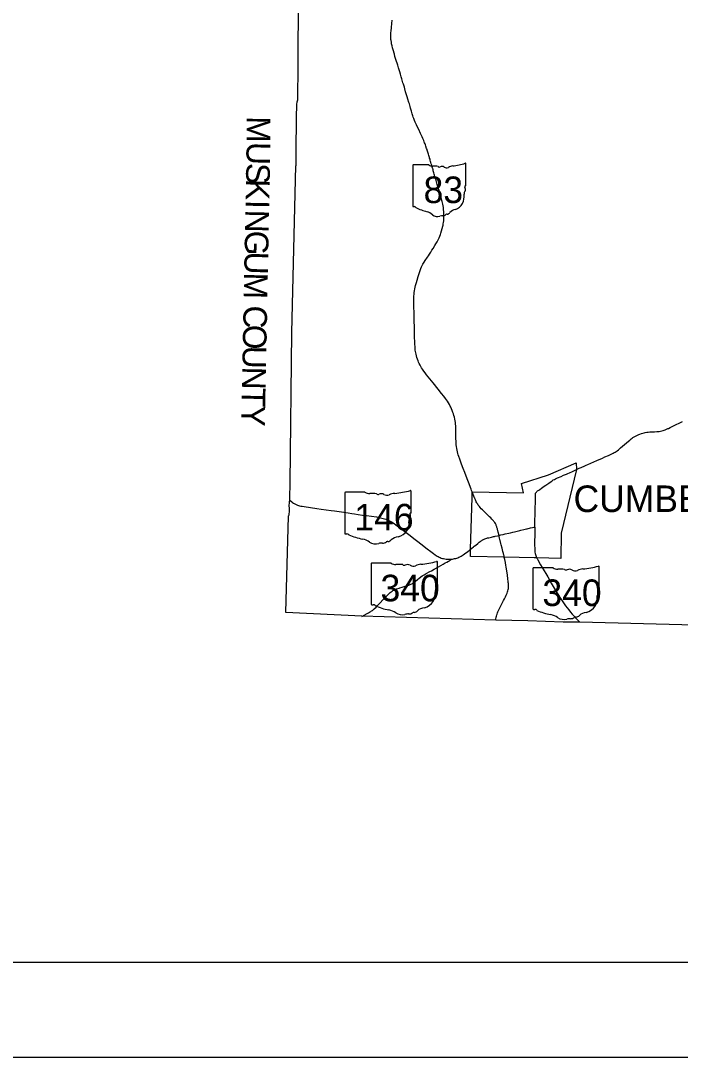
# Model space of a CAD drawing. Extents: x 1913970 to 2397567, y 78841 to 829347.
# Drawn here: x 2183521 to 2211369, y 653347 to 697090 of the extents above; entities that cross this region are included whole.
import ezdxf

# ---------------------------------------------------------------- set-up
doc = ezdxf.new("R2010")
doc.units = 0
for name, color, linetype in [('GM_X_Corporation', 7, 'Continuous'), ('GM_X_Corporation_Text', 7, 'Continuous'), ('GM_X_County', 7, 'Continuous'), ('GM_X_County_Text', 7, 'Continuous'), ('GM_X_State_Location', 7, 'Continuous'), ('GM_X_State_Route', 7, 'Continuous'), ('GM_X_State_Shield', 7, 'Continuous'), ('SH_Border', 7, 'Continuous'), ('SH_Cut_Line', 7, 'Continuous')]:
    doc.layers.add(name, color=color, linetype=linetype)

msp = doc.modelspace()

# ---------------------------------------------------------------- linework, layer by layer
at = {"layer": 'GM_X_Corporation'}
msp.add_lwpolyline([(2204669, 677556), (2205799, 677929), (2206980, 678432), (2206985, 678150), (2206345, 675471), (2206322, 674400), (2205310, 674419), (2205195, 674422), (2203938, 674447), (2202509, 674477), (2202514, 674791), (2202575, 676967), (2202581, 677202), (2204756, 677161)], close=True, dxfattribs=at)
at = {"layer": 'GM_X_County'}
msp.add_lwpolyline([(2214128, 671527), (2207126, 671715), (2206418, 671715), (2204928, 671762), (2203576, 671791), (2197927, 671957), (2194717, 672121), (2194830, 676185), (2194844, 676218), (2194849, 676237), (2194855, 676263), (2194859, 676298), (2194863, 676354), (2194864, 676439), (2194863, 676531), (2194861, 676609), (2194862, 676655), (2194864, 676714), (2194868, 676773), (2194870, 676792), (2194880, 676865), (2194883, 676960), (2194892, 677576), (2194965, 683939), (2195143, 690967), (2195146, 690986), (2195148, 690999), (2195149, 691013), (2195149, 691037), (2195154, 691313), (2195156, 691394), (2195156, 691508), (2195156, 691589), (2195156, 691736), (2195153, 691867), (2195151, 691995), (2195153, 692127), (2195156, 692218), (2195158, 692343), (2195162, 692618), (2195164, 692817), (2195168, 692981), (2195168, 693063), (2195169, 693128), (2195169, 693146), (2195169, 693170), (2195170, 693194), (2195175, 693373), (2195177, 693422), (2195180, 693471), (2195183, 693553), (2195185, 693590), (2195189, 693634), (2195191, 693650), (2195194, 693666), (2195197, 693682), (2195201, 693700), (2195207, 693718), (2195215, 693737), (2195235, 695229), (2195244, 698121)], dxfattribs=at)
at = {"layer": 'GM_X_State_Route'}
for points in [[(2200472, 686759), (2200499, 686813), (2200523, 686855), (2200553, 686905), (2200597, 686971), (2200690, 687109), (2200734, 687174), (2200779, 687243), (2200834, 687328), (2200882, 687402), (2200929, 687477), (2201007, 687602), (2201054, 687677), (2201098, 687754), (2201134, 687821), (2201160, 687874), (2201186, 687931), (2201214, 688001), (2201239, 688069), (2201261, 688128), (2201321, 688328), (2201344, 688416), (2201354, 688468), (2201364, 688522), (2201373, 688581), (2201380, 688649), (2201386, 688724), (2201387, 688766), (2201387, 688845), (2201385, 688933), (2201382, 689038), (2201377, 689107), (2201373, 689149), (2201366, 689204), (2201354, 689285), (2201342, 689353), (2201330, 689410), (2201318, 689458), (2201304, 689508), (2201269, 689632), (2201246, 689714), (2201208, 689846), (2201195, 689893), (2201183, 689934), (2201166, 689991), (2201153, 690032), (2201137, 690085), (2201121, 690135), (2201106, 690185), (2201090, 690238), (2201074, 690292), (2201059, 690346), (2201043, 690399), (2201026, 690462), (2201010, 690519), (2200995, 690570), (2200981, 690620), (2200966, 690674), (2200953, 690718), (2200941, 690762), (2200929, 690803), (2200918, 690841), (2200915, 690853), (2200908, 690875), (2200898, 690910), (2200890, 690938), (2200880, 690969), (2200873, 690995), (2200865, 691023), (2200855, 691057), (2200840, 691108), (2200827, 691155), (2200815, 691199), (2200802, 691243), (2200787, 691293), (2200778, 691325), (2200767, 691362), (2200756, 691400), (2200736, 691466), (2200725, 691500), (2200712, 691544), (2200685, 691627), (2200676, 691655), (2200660, 691702), (2200627, 691794), (2200609, 691847), (2200593, 691890), (2200575, 691939), (2200558, 691981), (2200538, 692030), (2200522, 692069), (2200513, 692090), (2200498, 692126), (2200472, 692186), (2200428, 692282), (2200405, 692332), (2200324, 692501), (2200280, 692593), (2200231, 692696), (2200180, 692807), (2200147, 692885), (2200116, 692961), (2200094, 693023), (2200078, 693070), (2200049, 693164), (2200020, 693268), (2199979, 693407), (2199959, 693473), (2199930, 693577), (2199913, 693634), (2199867, 693784), (2199840, 693872), (2199801, 694001), (2199774, 694089), (2199738, 694211), (2199718, 694280), (2199679, 694412), (2199659, 694475), (2199612, 694639), (2199586, 694724), (2199553, 694834), (2199523, 694938), (2199472, 695100), (2199437, 695217), (2199413, 695295), (2199389, 695370), (2199362, 695454), (2199349, 695498), (2199322, 695583), (2199296, 695674), (2199241, 695863), (2199221, 695940), (2199198, 696036), (2199182, 696113), (2199169, 696187), (2199159, 696256), (2199153, 696305), (2199150, 696361), (2199149, 696416), (2199150, 696492), (2199154, 696574), (2199160, 696663), (2199171, 696784), (2199175, 696826), (2199180, 696868), (2199186, 696917), (2199192, 696969), (2199197, 697008), (2199203, 697080), (2199205, 697109)], [(2202581, 677204), (2202557, 677262), (2202534, 677320), (2202424, 677615), (2202369, 677759), (2202271, 678020), (2202205, 678195), (2202136, 678379), (2202057, 678588), (2202019, 678696), (2201995, 678768), (2201977, 678830), (2201961, 678894), (2201945, 678964), (2201931, 679038), (2201918, 679119), (2201909, 679190), (2201903, 679259), (2201900, 679337), (2201898, 679465), (2201898, 679714), (2201897, 679859), (2201895, 679924), (2201891, 679990), (2201884, 680062), (2201875, 680134), (2201863, 680202), (2201848, 680276), (2201830, 680356), (2201810, 680433), (2201791, 680496), (2201768, 680564), (2201741, 680635), (2201710, 680711), (2201680, 680777), (2201654, 680830), (2201622, 680891), (2201578, 680968), (2201535, 681038), (2201498, 681093), (2201457, 681152), (2201387, 681244), (2201292, 681365), (2201150, 681541), (2200937, 681804), (2200660, 682149), (2200593, 682234), (2200539, 682305), (2200487, 682380), (2200448, 682440), (2200414, 682496), (2200381, 682557), (2200350, 682618), (2200321, 682680), (2200295, 682744), (2200270, 682811), (2200247, 682883), (2200227, 682952), (2200211, 683016), (2200199, 683076), (2200188, 683138), (2200181, 683190), (2200175, 683251), (2200169, 683333), (2200163, 683444), (2200152, 683835), (2200145, 684090), (2200141, 684215), (2200137, 684369), (2200133, 684546), (2200127, 684743), (2200119, 685025), (2200116, 685172), (2200116, 685290), (2200118, 685388), (2200123, 685470), (2200129, 685548), (2200137, 685620), (2200149, 685697), (2200162, 685775), (2200179, 685852), (2200196, 685921), (2200228, 686042), (2200256, 686139), (2200304, 686296), (2200346, 686430), (2200385, 686545), (2200417, 686631), (2200444, 686698), (2200469, 686754), (2200472, 686759)], [(2206986, 678148), (2207105, 678201), (2207186, 678237), (2207336, 678303), (2207402, 678332), (2207468, 678361), (2207591, 678416), (2207723, 678474), (2207840, 678526), (2208082, 678636), (2208190, 678684), (2208337, 678748), (2208479, 678810), (2208541, 678839), (2208584, 678862), (2208626, 678887), (2208661, 678911), (2208701, 678940), (2208759, 678988), (2208844, 679060), (2209013, 679205), (2209098, 679277), (2209183, 679350), (2209236, 679394), (2209293, 679439), (2209343, 679476), (2209370, 679495), (2209420, 679529), (2209508, 679577), (2209564, 679605), (2209615, 679628), (2209667, 679649), (2209726, 679669), (2209786, 679687), (2209843, 679702), (2209892, 679712), (2209950, 679722), (2210012, 679730), (2210078, 679735), (2210156, 679739), (2210287, 679745), (2210372, 679751), (2210431, 679756), (2210473, 679762), (2210528, 679772), (2210585, 679785), (2210645, 679800), (2210686, 679812), (2210732, 679828), (2210790, 679851), (2210850, 679877), (2210874, 679888)], [(2210874, 679888), (2210945, 679921), (2211054, 679974), (2211461, 680179)], [(2205273, 677172), (2205282, 677184), (2205297, 677201), (2205319, 677222), (2205347, 677245), (2205400, 677285), (2205439, 677312), (2205513, 677365), (2205622, 677443), (2205694, 677494), (2205817, 677581), (2205911, 677647), (2205916, 677651), (2205957, 677679), (2206004, 677709), (2206054, 677736), (2206104, 677760), (2206159, 677785), (2206185, 677796), (2206345, 677863), (2206445, 677906), (2206562, 677958), (2206625, 677985), (2206688, 678013), (2206816, 678072), (2206986, 678148)], [(2203716, 675371), (2203682, 675501), (2203662, 675579), (2203655, 675605), (2203645, 675646), (2203639, 675671), (2203629, 675709), (2203621, 675737), (2203612, 675765), (2203602, 675793), (2203593, 675814), (2203579, 675841), (2203561, 675872), (2203538, 675908), (2203521, 675932), (2203497, 675963), (2203480, 675983), (2203465, 676000), (2203439, 676029), (2203413, 676058), (2203368, 676106), (2203317, 676157), (2203262, 676210), (2203229, 676241), (2203187, 676282), (2203147, 676321), (2203112, 676356), (2203013, 676451), (2202968, 676494), (2202920, 676547), (2202918, 676550), (2202887, 676587), (2202855, 676628), (2202838, 676652), (2202816, 676685), (2202800, 676713), (2202781, 676747), (2202757, 676794), (2202723, 676865), (2202696, 676928), (2202688, 676944), (2202684, 676955), (2202652, 677030), (2202627, 677090), (2202583, 677199), (2202581, 677204)], [(2205225, 675723), (2205226, 675800), (2205229, 675885), (2205229, 675930), (2205232, 676010), (2205238, 676236), (2205240, 676341), (2205242, 676436), (2205245, 676502), (2205247, 676587), (2205251, 676701), (2205251, 676734), (2205252, 676789), (2205252, 676812), (2205252, 676828), (2205251, 676916), (2205250, 676982), (2205249, 677057), (2205249, 677104), (2205251, 677120), (2205255, 677137), (2205262, 677153), (2205270, 677168), (2205273, 677172)], [(2194881, 676862), (2194965, 676792), (2195002, 676764), (2195043, 676737), (2195088, 676709), (2195129, 676687), (2195173, 676666), (2195210, 676651), (2195247, 676638), (2195295, 676624), (2195352, 676610), (2195407, 676599), (2195488, 676586), (2196024, 676509), (2196203, 676483), (2196622, 676423), (2196775, 676402), (2197167, 676344), (2197349, 676319), (2197495, 676297), (2197609, 676280), (2197762, 676258), (2197957, 676231), (2198119, 676207), (2198337, 676178), (2198538, 676147), (2198645, 676130), (2198712, 676116), (2198772, 676101), (2198829, 676085), (2198885, 676068), (2198934, 676050), (2199004, 676022), (2199067, 675994), (2199123, 675967), (2199172, 675941), (2199220, 675912), (2199288, 675868), (2199353, 675823), (2199413, 675778), (2199677, 675577), (2199902, 675402), (2200171, 675196), (2200288, 675106), (2200412, 675010), (2200677, 674805), (2200836, 674684), (2200946, 674601), (2201013, 674552), (2201056, 674523), (2201098, 674497), (2201142, 674473), (2201186, 674452), (2201232, 674432), (2201278, 674416), (2201326, 674402), (2201374, 674391), (2201426, 674381), (2201484, 674372), (2201540, 674366), (2201589, 674364), (2201629, 674363), (2201709, 674366)], [(2203716, 675371), (2203796, 675390), (2203888, 675411), (2203977, 675432), (2204130, 675468), (2204201, 675485), (2204293, 675506), (2204370, 675524), (2204545, 675566), (2204595, 675578)], [(2204595, 675578), (2204631, 675587), (2204761, 675618), (2204869, 675644), (2204900, 675652)], [(2204900, 675652), (2205042, 675685), (2205134, 675707), (2205181, 675717), (2205195, 675720), (2205209, 675722), (2205225, 675723)], [(2205225, 675723), (2205224, 675562), (2205225, 675408), (2205224, 675385), (2205223, 675346), (2205222, 675275), (2205220, 675210), (2205217, 675088), (2205219, 674996), (2205219, 674959)], [(2202511, 674785), (2202515, 674788), (2202571, 674832), (2202638, 674885), (2202672, 674911), (2202734, 674960), (2202818, 675027), (2202881, 675079), (2202919, 675110), (2202945, 675130), (2202958, 675140), (2202987, 675160), (2203019, 675182), (2203027, 675187), (2203056, 675202), (2203085, 675216), (2203118, 675229), (2203155, 675241), (2203199, 675253), (2203234, 675261), (2203282, 675272), (2203394, 675298), (2203480, 675318), (2203530, 675329)], [(2203530, 675329), (2203559, 675335), (2203652, 675357), (2203716, 675371)], [(2203939, 674444), (2203926, 674503), (2203918, 674542), (2203903, 674609), (2203881, 674698), (2203848, 674828), (2203813, 674966), (2203798, 675025), (2203764, 675155), (2203757, 675183), (2203735, 675265), (2203728, 675300), (2203722, 675327), (2203718, 675350), (2203716, 675371)], [(2201709, 674366), (2201723, 674367), (2201737, 674368), (2201758, 674371), (2201838, 674389), (2201886, 674401), (2201933, 674415), (2201973, 674429), (2202016, 674446), (2202064, 674468), (2202114, 674493), (2202154, 674517), (2202200, 674547), (2202262, 674591), (2202392, 674691), (2202466, 674749), (2202511, 674785)], [(2205219, 674959), (2205221, 674819), (2205224, 674748), (2205227, 674704), (2205233, 674665), (2205243, 674613), (2205254, 674565), (2205267, 674524), (2205281, 674483), (2205309, 674421)], [(2197928, 671954), (2198023, 672006), (2198151, 672072), (2198206, 672101), (2198252, 672126), (2198303, 672157), (2198338, 672181), (2198370, 672204), (2198395, 672226), (2198446, 672272), (2198523, 672348), (2198586, 672411), (2198665, 672490), (2198703, 672530), (2198814, 672647), (2198865, 672702), (2198907, 672748), (2198938, 672782), (2198974, 672819), (2199023, 672868), (2199076, 672917), (2199120, 672955), (2199161, 672988), (2199198, 673016), (2199235, 673041), (2199275, 673064), (2199312, 673083), (2199342, 673097), (2199381, 673112), (2199437, 673131), (2199496, 673150), (2199527, 673161), (2199621, 673192), (2199664, 673206), (2199711, 673220), (2199755, 673233), (2199834, 673254), (2199904, 673275), (2199963, 673295), (2199996, 673310), (2200029, 673325), (2200058, 673342), (2200088, 673361), (2200093, 673365), (2200109, 673378), (2200135, 673398), (2200194, 673444), (2200278, 673512), (2200339, 673560), (2200394, 673602), (2200420, 673621), (2200473, 673659), (2200503, 673679), (2200550, 673708), (2200635, 673758), (2200795, 673847), (2200859, 673882), (2200976, 673947), (2201154, 674046), (2201260, 674105), (2201364, 674162), (2201447, 674206), (2201508, 674238), (2201586, 674280), (2201625, 674303), (2201657, 674322), (2201686, 674345), (2201709, 674366)], [(2203577, 671788), (2203580, 671803), (2203586, 671839), (2203599, 671917), (2203609, 671968), (2203621, 672015), (2203632, 672053), (2203647, 672096), (2203663, 672139), (2203680, 672178), (2203703, 672229), (2203745, 672310), (2203838, 672488), (2203879, 672566), (2203906, 672618), (2203945, 672694), (2203987, 672780), (2204016, 672843), (2204054, 672930), (2204080, 672994), (2204094, 673038), (2204105, 673083), (2204111, 673126), (2204114, 673172), (2204115, 673228), (2204114, 673261), (2204113, 673291), (2204110, 673343), (2204106, 673382), (2204101, 673428), (2204089, 673539), (2204071, 673692), (2204057, 673789), (2204046, 673858), (2204015, 674042), (2204005, 674100), (2203983, 674223), (2203956, 674358), (2203939, 674444)], [(2205309, 674421), (2205311, 674416), (2205321, 674397), (2205351, 674342), (2205473, 674132), (2205542, 674013), (2205771, 673619), (2205922, 673357), (2206131, 673001), (2206242, 672815), (2206284, 672748), (2206347, 672652), (2206435, 672525), (2206521, 672405), (2206586, 672318), (2206657, 672228), (2206738, 672128), (2206806, 672049), (2206877, 671971), (2206988, 671854), (2207127, 671712)]]:
    msp.add_lwpolyline(points, dxfattribs=at)
at = {"layer": 'GM_X_State_Shield'}
for p, q in [((2200075, 690976), (2200075, 689275)), ((2200753, 691005), (2200097, 691005)), ((2202316, 690158), (2202316, 691047)), ((2202316, 690158), (2202316, 690158)), ((2197206, 677161), (2197206, 675460)), ((2198054, 677191), (2197234, 677191)), ((2200008, 676343), (2200008, 677233)), ((2200008, 676343), (2200008, 676343)), ((2198313, 674171), (2198313, 672469)), ((2199161, 674200), (2198341, 674200)), ((2201115, 673352), (2201115, 674242)), ((2205149, 673972), (2205149, 672271)), ((2205997, 674001), (2205176, 674001)), ((2207951, 673153), (2207951, 674043)), ((2201115, 673352), (2201115, 673352)), ((2207950, 673154), (2207951, 673153))]:
    msp.add_line(p, q, dxfattribs=at)
for centre, radius, start, end in [((2200101, 690980), 26, 98.1301, 188.1301), ((2200910, 691203), 252, 231.6195, 271.1119), ((2200993, 690050), 904, 80.4867, 94.9883), ((2201199, 690988), 72.7, 219.7921, 297.1024), ((2201305, 690792), 151, 54.4667, 119.1411), ((2201500, 691061), 182, 233.8562, 294.8282), ((2201821, 690486), 478, 97.3462, 120.7689), ((2201518, 693325), 2377, 275.8445, 288.9065), ((2202291, 691051), 25, 351.8621, 97.738), ((2202406, 689785), 169, 136.8065, 186.9296), ((2202311, 690092), 38.6, 107.944, 210.337), ((2202065, 689980), 232, 340.033, 23.6496), ((2202290, 690154), 26.7, 289.6038, 7.7341), ((2201651, 689672), 595, 292.3089, 8.9858), ((2200101, 689271), 26.2, 171.9584, 258.3066), ((2200105, 689445), 200, 267.339, 280.6039), ((2200146, 689177), 72.1, 29.7484, 93.2717), ((2201056, 690705), 1716, 240.4129, 257.1985), ((2200544, 688511), 537, 47.1842, 75.836), ((2201489, 689110), 192, 282.8732, 323.2771), ((2201902, 688797), 326, 94.4031, 142.5768), ((2201125, 689168), 341, 230.7004, 286.2918), ((2201322, 688580), 280, 85.6951, 111.2099), ((2201347, 689041), 182, 268.777, 315.5493), ((2201511, 688876), 51.1, 65.7517, 132.6484)]:
    msp.add_arc(centre, radius, start, end, dxfattribs=at)
for centre, major_axis, start_param, end_param in [((2197238, 677165), (32.5, 0), 1.712693, 3.28349), ((2198250, 677388), (315, 0), 4.042523, 4.731795), ((2199010, 679510), (2971, 0), 4.814394, 5.042369), ((2199977, 677236), (31.2, 0), 6.141152, 7.989035), ((2198354, 676235), (1130, 0), 1.404758, 1.657858), ((2198611, 677174), (90.8, 0), 3.836095, 5.185415), ((2198744, 676977), (189, 0), 0.950623, 2.079405), ((2198988, 677247), (227, 0), 4.081561, 5.145723), ((2199389, 676671), (598, 0), 1.699011, 2.107814), ((2200001, 676277), (48.3, 0), 1.883978, 3.671073), ((2199975, 676339), (33.4, 0), 5.05454, 6.418171), ((2199176, 675857), (743, 0), 5.101752, 6.440018), ((2200120, 675970), (211, 0), 2.387724, 3.262537), ((2199694, 676165), (290, 0), 5.934695, 6.695948), ((2197238, 675456), (32.7, 0), 3.00124, 4.508301), ((2197243, 675630), (250, 0), 4.665946, 4.897461), ((2197295, 675362), (90.1, 0), 0.519207, 1.627899), ((2198432, 676890), (2146, 0), 4.195997, 4.488961), ((2197793, 674696), (671, 0), 0.823519, 1.323587), ((2198519, 675353), (426, 0), 4.026481, 4.996735), ((2198765, 674765), (350, 0), 1.495662, 1.94098), ((2198796, 675226), (227, 0), 4.691044, 5.507374), ((2199001, 675061), (63.9, 0), 1.147584, 2.315152), ((2198974, 675295), (240, 0), 4.937069, 5.64225), ((2199490, 674982), (407, 0), 1.647645, 2.488434), ((2198345, 674174), (32.5, 0), 1.712693, 3.28349), ((2199357, 674397), (315, 0), 4.042523, 4.731795), ((2199461, 673245), (1130, 0), 1.404758, 1.657858), ((2199718, 674183), (90.8, 0), 3.836095, 5.185415), ((2199851, 673986), (189, 0), 0.950623, 2.079405), ((2200095, 674256), (227, 0), 4.081561, 5.145723), ((2200496, 673680), (598, 0), 1.699011, 2.107814), ((2200117, 676519), (2971, 0), 4.814394, 5.042369), ((2201084, 674246), (31.2, 0), 6.141152, 7.989035), ((2205181, 673976), (32.5, 0), 1.712693, 3.28349), ((2206192, 674199), (315, 0), 4.042523, 4.731795), ((2206297, 673046), (1130, 0), 1.404758, 1.657858), ((2206553, 673984), (90.8, 0), 3.836095, 5.185415), ((2206687, 673788), (189, 0), 0.950623, 2.079405), ((2206930, 674057), (227, 0), 4.081561, 5.145723), ((2207332, 673482), (598, 0), 1.699011, 2.107814), ((2206953, 676321), (2971, 0), 4.814394, 5.042369), ((2207919, 674047), (31.2, 0), 6.141152, 7.989035), ((2201108, 673287), (48.3, 0), 1.883978, 3.671073), ((2200801, 673174), (290, 0), 5.934695, 6.695948), ((2201082, 673349), (33.4, 0), 5.05454, 6.418171), ((2200283, 672866), (743, 0), 5.101752, 6.440018), ((2201227, 672980), (211, 0), 2.387724, 3.262537), ((2208062, 672781), (211, 0), 2.387724, 3.262537), ((2207943, 673088), (48.3, 0), 1.883978, 3.671073), ((2207636, 672976), (290, 0), 5.934695, 6.695948), ((2207917, 673150), (33.4, 0), 5.05454, 6.418171), ((2198346, 672466), (32.7, 0), 3.00124, 4.508301), ((2198351, 672640), (250, 0), 4.665946, 4.897461), ((2198402, 672371), (90.1, 0), 0.519207, 1.627899), ((2199539, 673900), (2146, 0), 4.195997, 4.488961), ((2207119, 672668), (743, 0), 5.101752, 6.440018), ((2198900, 671705), (671, 0), 0.823519, 1.323587), ((2199626, 672363), (426, 0), 4.026481, 4.996735), ((2199872, 671775), (350, 0), 1.495662, 1.94098), ((2199903, 672235), (227, 0), 4.691044, 5.507374), ((2200108, 672071), (63.9, 0), 1.147584, 2.315152), ((2200081, 672305), (240, 0), 4.937069, 5.64225), ((2200597, 671992), (407, 0), 1.647645, 2.488434), ((2205181, 672267), (32.7, 0), 3.00124, 4.508301), ((2205186, 672441), (250, 0), 4.665946, 4.897461), ((2205237, 672173), (90.1, 0), 0.519207, 1.627899), ((2206375, 673701), (2146, 0), 4.195997, 4.488961), ((2205735, 671507), (671, 0), 0.823519, 1.323587), ((2206739, 672037), (227, 0), 4.691044, 5.507374), ((2206944, 671872), (63.9, 0), 1.147584, 2.315152), ((2206917, 672106), (240, 0), 4.937069, 5.64225), ((2207432, 671793), (407, 0), 1.647645, 2.488434), ((2206461, 672164), (426, 0), 4.026481, 4.996735), ((2206707, 671576), (350, 0), 1.495662, 1.94098)]:
    msp.add_ellipse(centre, major_axis=major_axis, ratio=0.8, start_param=start_param, end_param=end_param, dxfattribs=at)
at = {"layer": 'SH_Border'}
msp.add_lwpolyline([(2137567, 825347), (2393567, 825347), (2393567, 657347), (2137567, 657347)], close=True, dxfattribs=at)
at = {"layer": 'SH_Cut_Line'}
msp.add_lwpolyline([(2125567, 653347), (2397567, 653347), (2397567, 829347), (2125567, 829347)], close=True, dxfattribs=at)

# ---------------------------------------------------------------- texts
at = {"layer": 'GM_X_Corporation_Text'}
msp.add_text('CUMBERLAND', height=1120, rotation=0, dxfattribs=at).set_placement((2206862, 676357))
at = {"layer": 'GM_X_County_Text'}
for s, rotation, p in [('M', 269.5558, (2193067, 693062)), ('U', 269.1779, (2193058, 691977)), ('S', 269.0462, (2193046, 691093)), ('K', 268.9125, (2193034, 690417)), ('I', 268.8718, (2193018, 689533)), ('N', 268.856, (2193010, 689123)), ('G', 268.8538, (2192992, 688239)), ('U', 268.8516, (2192974, 687355)), ('M', 268.853, (2192957, 686471)), ('C', 268.8539, (2192929, 685081)), ('O', 268.8516, (2192912, 684267)), ('U', 268.8536, (2192895, 683383)), ('N', 268.8538, (2192877, 682498)), ('T', 268.8531, (2192859, 681614)), ('Y', 268.8516, (2192844, 680866))]:
    msp.add_text(s, height=1000, rotation=rotation, dxfattribs=at).set_placement(p)
at = {"layer": 'GM_X_State_Location'}
for s, p in [('83', (2201645, 679692)), ('146', (2200435, 674597)), ('340', (2199401, 673039))]:
    msp.add_text(s, height=1, rotation=0, dxfattribs=at).set_placement(p)
for s, p in [('s', (2201897, 679765)), ('r', (2201897, 679765)), ('s', (2200788, 674669)), ('r', (2200788, 674669)), ('s', (2199754, 673112)), ('r', (2199754, 673112))]:
    msp.add_text(s, height=1, dxfattribs=at).set_placement(p)
at = {"layer": 'GM_X_State_Shield'}
for s, p in [('83', (2200531, 689395)), ('146', (2197609, 675580)), ('340', (2198712, 672589)), ('340', (2205548, 672391))]:
    msp.add_text(s, height=1120.7, dxfattribs=at).set_placement(p)

doc.saveas('drawing.dxf')
